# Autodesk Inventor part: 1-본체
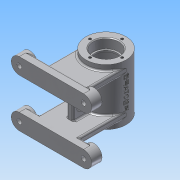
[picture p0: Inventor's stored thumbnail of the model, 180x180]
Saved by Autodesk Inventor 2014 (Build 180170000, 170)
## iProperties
Created: 2015-11
Part Number: 1-본체
Material: 알루미늄 6061
Document SubType Name: Modeling
Designer: 27
Density: 2.71 g/cm^3
Appearance: 알루미늄 - 평지
Mass: 359.021 g
Surface Area: 460.312 cm^2
Volume: 132.48 cm^3
Author: 27
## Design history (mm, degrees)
sketch "스케치1"
  geometry: C1 r 25 at (0, 0); 1 further point
  constraints: 1 centre point, 1 coincident
  dimensions: "d0" = 50 diameter of C1
extrude "돌출1" new body sketch "스케치1" distance "d1" = 70; taper "d2" = 0 deg
node "작업 평면1"
sketch "스케치2"
  geometry: L1 (25, 70)-(-25, 70) reference; L2 (-25, 0)-(25, 0) reference; L3 (-25, 0)-(-25, 70) reference; L4 (25, 0)-(25, 70) reference; L5 (-40, 75)-(40, 75); L6 (-40, 55)-(40, 55); A1 r 10 centre (-40, 65) between (-40, 75) and (-40, 55); A2 r 10 centre (40, 65) between (40, 55) and (40, 75); 7 further points
  constraints: 5 end point, 4 midpoint, 4 point on circle, 3 vertical alignment, 2 centre point, 2 horizontal alignment, 2 tangent, 1 parallel, 1 perpendicular
  dimensions: "d4" = 20 diameter of A1; "d5" = 20 diameter of A2; "d6" = 80 distance of A2.centre A1.centre; "d9" = 40 distance from line of L5 point (0, 35)
extrude "돌출2" join sketch "스케치2" distance "d10" = 10; taper "d11" = 0 deg
sketch "스케치3"
  geometry: C1 r 10 at (-40, -65); C2 r 10 at (40, -65); A1 r 10 centre (40, -65) between (40, -75) and (40, -55) reference; A2 r 10 centre (-40, -65) between (-40, -55) and (-40, -75) reference; 1 further point
  constraints: 2 centre point, 2 coincident, 1 concentric
  dimensions: "d12" = 20 diameter of C1
extrude "돌출3" join sketch "스케치3" distance "d13" = 3; taper "d14" = 0 deg
node "작업 평면3"
  node "작업 평면2"
sketch "스케치4"
  geometry: L1 (80, 0)-(0, 0) reference; L2 (0, 0)-(0, 10) reference; L3 (80, 10)-(0, 10) reference; L4 (80, 0)-(80, 10) reference; L5 (15, 68)-(15, 10); L6 (65, 68)-(65, 10); L7 (15, 10)-(65, 10); L8 (15, 68)-(65, 68); A1 r 25 centre (40, 68) between (15, 68) and (65, 68) reference; 1 further point
  constraints: 8 end point, 2 parallel, 2 perpendicular, 2 point on circle, 2 point on line, 2 tangent
extrude "돌출4" join sketch "스케치4" distance "d16" = 8; taper "d17" = 0 deg
node "작업 평면4"
node "작업 평면6"
sketch "스케치5"
  geometry: L1 (-25, 0)-(-25, 70) reference; L2 (-58, 55)-(0, 55) reference; L3 (-58, 15)-(0, 15) reference; L4 (-45, 57.054)-(-45, 11.993); L5 (-45, 57.054)-(-19.914, 57.054); L6 (-19.914, 57.054)-(-19.914, 11.993); L7 (-19.914, 11.993)-(-45, 11.993); 1 further point
  constraints: 8 end point, 3 perpendicular, 1 parallel
  dimensions: "d19" = 20 distance between parallel lines of L4 L1; "d22" = 5.08556 distance between parallel lines of L1 L6; "d23" = 3.00724 distance between parallel lines of L7 L3; "d24" = 2.05433 distance between parallel lines of L2 L5
extrude "돌출5" join sketch "스케치5" stored distance "d25" = 8; taper "d26" = 0 deg
node "작업 평면8"
sketch "스케치7"
  geometry: L1 (25, 0)-(25, 70) reference; L2 (-25, 0)-(-25, 70) reference; L3 (-25, 0)-(25, 0) reference; L4 (25, 70)-(-25, 70) reference; C1 r 5 at (0, 35); 3 further points
  constraints: 2 midpoint, 1 centre point, 1 horizontal alignment, 1 vertical alignment
  dimensions: "d29" = 10 diameter of C1
extrude "돌출6" join sketch "스케치7" stored distance "d30" = 8; taper "d31" = 0 deg
sketch "스케치8"
  geometry: L1 (15, -24.678)-(55, -24.678) reference; L2 (55, -24.678)-(55, -45) reference; L3 (27, -31.5)-(43, -31.5); L4 (43, -38.5)-(27, -38.5); L5 (-5, -68)-(15, -68) reference; A1 r 3.5 centre (43, -35) between (43, -38.5) and (43, -31.5); A2 r 3.5 centre (27, -35) between (27, -31.5) and (27, -38.5); 3 further points
  constraints: 4 end point, 4 point on circle, 4 tangent, 2 centre point, 2 midpoint, 1 parallel, 1 perpendicular, 1 vertical alignment
  dimensions: "d32" = 23 dimension on A1 A2; "d33" = 3.5 radius of A1; "d34" = 33 distance from line of A2.centre L5
extrude "돌출7" cut sketch "스케치8" stored distance "d35" = 8; taper "d36" = 0 deg
hole "구멍1" diameter "d39" = 28; stored, may be unused: countersink angle "d43" = 90 deg, drill point angle "d45" = 0 deg; dims "d40" = 6, "d41" = 32, "d42" = 12, "d44" = 14, "d59" = 10, "d60" = 10
hole "구멍2" diameter "d48" = 28; stored, may be unused: countersink angle "d52" = 90 deg, drill point angle "d54" = 0 deg; dims "d49" = 6, "d50" = 32, "d51" = 12, "d53" = 14, "d61" = 10, "d62" = 10
node "작업 평면9"
sketch "스케치10"
  geometry: C1 r 14 at (0, 0) reference; 1 further point
  constraints: 1 coincident
hole "구멍3" sketch "스케치10" at (0, 0) diameter "d57" = 42; stored, may be unused: countersink angle "d65" = 90 deg, drill point angle "d67" = 0 deg; dims "d58" = 6, "d63" = 32, "d64" = 12, "d66" = 42
node "작업 평면10"
sketch "스케치11"
  geometry: L1 (0, 0)-(14, -24.249); A1 r 25 centre (0, 0) between (-25, 0) and (-4, -24.678) reference; A2 r 25 centre (0, 0) between (4, -24.678) and (25, 0) reference; A3 r 25 centre (0, 0) between (-25, 0) and (25, 0) reference; 1 further point
  constraints: 2 end point, 1 point on circle
  dimensions: "d68" = 30 deg dimension on L1.start point (0, -25) L1.end; "d69" = 28 distance of L1.start L1.end
node "작업 평면11"
sketch "스케치12"
  geometry: C1 r 6 at (0, 0); 2 further points
  constraints: 1 centre point, 1 coincident
  dimensions: "d70" = 12 diameter of C1
extrude "돌출8" join sketch "스케치12" stored distance "d71" = 8; taper "d72" = 0 deg
hole "구멍4" diameter "d75" = 5.188; stored, may be unused: countersink angle "d79" = 90 deg, drill point angle "d81" = 0 deg; dims "d73" = 10, "d74" = 10, "d76" = 6, "d77" = 32, "d78" = 12, "d80" = 42
hole "구멍5" diameter "d84" = 5.188; stored, may be unused: countersink angle "d88" = 90 deg, drill point angle "d90" = 0 deg; dims "d82" = 10, "d83" = 10, "d85" = 6, "d86" = 32, "d87" = 12, "d89" = 42
sketch "스케치13"
  geometry: C1 r 16 at (0, 0) reference; C2 r 25 at (0, 0) reference; A1 r 20 centre (0, 0) between (0, 20) and (0, -20); 2 further points
  constraints: 4 point on circle, 2 horizontal alignment, 2 vertical alignment, 1 centre point, 1 coincident
  dimensions: "d91" = 40 diameter of A1
hole "구멍6" sketch "스케치13" at (0, 20), (0, -20), (-20, 0), (20, 0) diameter "d92" = 3.242; stored, may be unused: countersink angle "d96" = 90 deg, drill point angle "d98" = 118 deg; dims "d93" = 8, "d94" = 32, "d95" = 12, "d97" = 10
node "작업 평면12"
node "작업 평면13"
sketch "스케치14"
  geometry: L1 (25, 0)-(25, 70) reference; L2 (25, 70)-(-25, 70) reference; L3 (-25, 0)-(25, 0) reference; L4 (-24.678, 55)-(-24.678, 15) reference; 2 further points
  constraints: 1 other
  dimensions: "d100" = 25 distance from line of point (0, 35) L1; "d101" = 35 distance from line of L2 point (0, 35)
feature "엠보싱1" sketch "스케치14" dims "d4" = 20, "d5" = 20, "d6" = 80, "d9" = 40, "d102" = 0.5, "d103" = 0
sketch "스케치15"
  geometry: C1 r 10 at (0, 0) reference; 1 further point
hole "구멍7" diameter "d106" = 6; stored, may be unused: countersink angle "d110" = 90 deg, drill point angle "d112" = 0 deg; dims "d104" = 10, "d105" = 10, "d107" = 8, "d108" = 12, "d109" = 4, "d111" = 10
hole "구멍8" diameter "d115" = 6; stored, may be unused: countersink angle "d119" = 90 deg, drill point angle "d121" = 0 deg; dims "d113" = 10, "d114" = 10, "d116" = 8, "d117" = 12, "d118" = 4, "d120" = 10
hole "구멍9" diameter "d124" = 6; stored, may be unused: countersink angle "d128" = 90 deg, drill point angle "d130" = 0 deg; dims "d122" = 10, "d123" = 10, "d125" = 8, "d126" = 12, "d127" = 4, "d129" = 10
hole "구멍10" diameter "d133" = 6; stored, may be unused: countersink angle "d137" = 90 deg, drill point angle "d139" = 0 deg; dims "d131" = 10, "d132" = 10, "d134" = 8, "d135" = 12, "d136" = 4, "d138" = 10
fillet "모깎기1" dims "d140" = 2
fillet "모깎기2" dims "d141" = 2
fillet "모깎기3" dims "d142" = 2
fillet "모깎기4" dims "d143" = 2
fillet "모깎기5" dims "d144" = 2
chamfer "모따기1" distance "d145" = 1; stored, may be unused: second distance "d146" = 2, angle "d147" = 45 deg
fillet "모깎기6" dims "d148" = 0.3
fillet "모깎기7" dims "d149" = 3
fillet "모깎기8" dims "d150" = 0.3
node "솔리드1"
mirror "대칭1"
mirror "대칭2"
mirror "대칭3"
node "투영된 루프1"
node "투영된 루프2"
node "투영된 루프3"
node "작업 평면5"
other parameters: "d3" = -68, "d18" = 0, "d28" = 28, "d99" = 26
